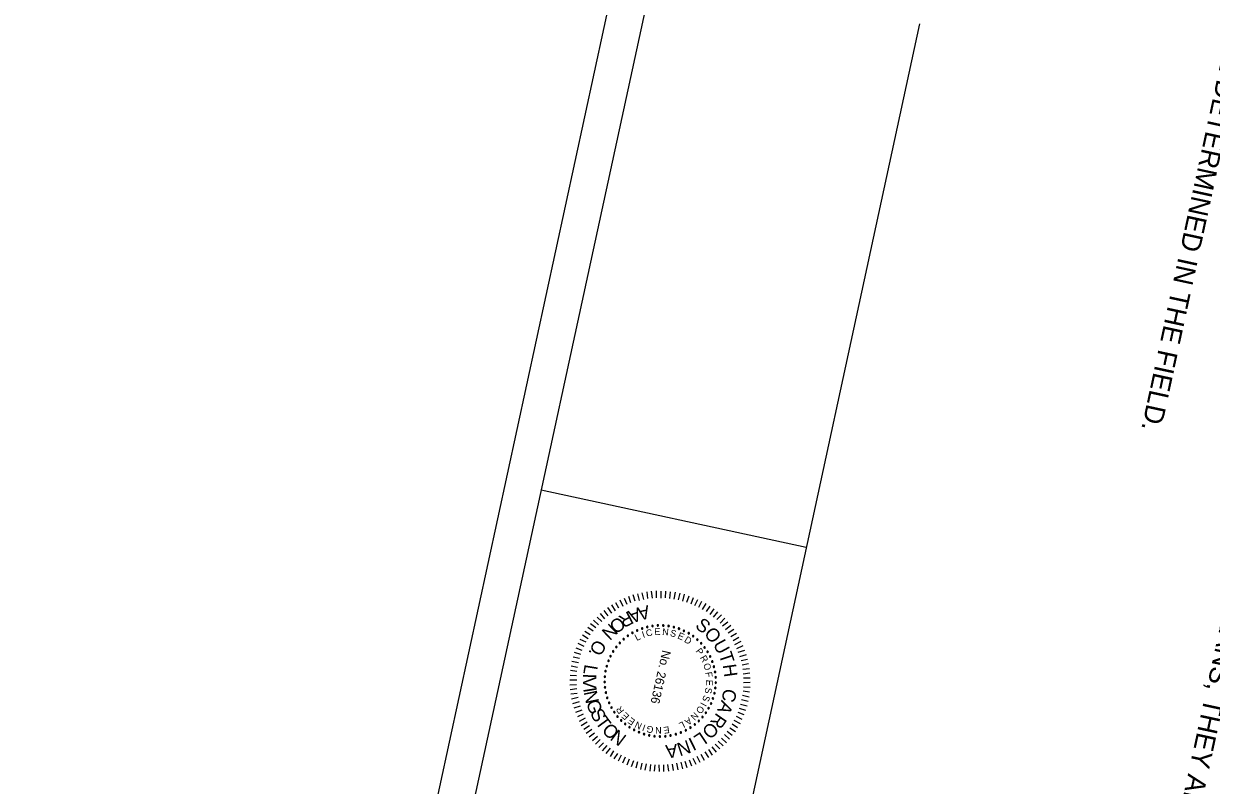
# Model space of a CAD drawing. Extents: x 1897817 to 2050613, y 442539 to 798440.
# Drawn here: x 1976813 to 1977576, y 783723 to 784212 of the extents above; entities that cross this region are included whole.
import ezdxf

# ---------------------------------------------------------------- set-up
doc = ezdxf.new("R2010")
doc.units = 0
for name, color, linetype in [('Default', 7, 'Continuous'), ('RD_SHT_Bndy', 7, 'Continuous'), ('RD_SHT_IplotShp', 7, 'Continuous')]:
    doc.layers.add(name, color=color, linetype=linetype)

msp = doc.modelspace()

# ---------------------------------------------------------------- linework, layer by layer
at = {"layer": 'Default'}
for p, q in [((1977203.28, 783839.73), (1977201.96, 783843.86)), ((1977206.14, 783840.79), (1977204.81, 783844.92)), ((1977208.89, 783841.39), (1977207.72, 783845.67)), ((1977211.58, 783842), (1977210.6, 783846.3)), ((1977214.33, 783842.6), (1977213.77, 783846.86)), ((1977217.12, 783842.82), (1977216.61, 783847.32)), ((1977219.79, 783843.07), (1977219.74, 783847.41)), ((1977222.74, 783842.9), (1977222.76, 783847.33)), ((1977225.56, 783842.99), (1977225.85, 783847.25)), ((1977228.4, 783842.66), (1977228.82, 783846.94)), ((1977231.05, 783842.24), (1977231.91, 783846.61)), ((1977233.97, 783841.71), (1977234.93, 783845.93)), ((1977236.73, 783840.96), (1977237.7, 783845.31)), ((1977239.35, 783840.19), (1977240.75, 783844.26)), ((1977242.07, 783839.27), (1977243.51, 783843.27)), ((1977191.04, 783833.23), (1977188.56, 783836.78)), ((1977193.51, 783834.75), (1977191.12, 783838.45)), ((1977195.7, 783836.32), (1977193.58, 783839.91)), ((1977198.33, 783837.5), (1977196.43, 783841.46)), ((1977200.98, 783838.72), (1977199.25, 783842.64)), ((1977244.34, 783838.03), (1977246.34, 783842.03)), ((1977247.08, 783836.93), (1977248.99, 783840.82)), ((1977249.33, 783835.57), (1977251.77, 783839.4)), ((1977251.87, 783834.15), (1977254.2, 783837.76)), ((1977254.21, 783832.4), (1977256.77, 783835.9)), ((1977182.61, 783825.76), (1977179.43, 783828.67)), ((1977184.65, 783827.8), (1977181.59, 783830.68)), ((1977186.56, 783829.55), (1977183.92, 783832.95)), ((1977188.81, 783831.42), (1977186.24, 783834.86)), ((1977256.44, 783830.68), (1977259.16, 783834.09)), ((1977258.5, 783829), (1977261.46, 783832.17)), ((1977260.63, 783826.82), (1977263.65, 783829.97)), ((1977177.29, 783819.17), (1977173.79, 783821.48)), ((1977179.03, 783821.51), (1977175.63, 783823.98)), ((1977180.75, 783823.74), (1977177.39, 783826.39)), ((1977262.27, 783824.93), (1977265.69, 783827.69)), ((1977264.14, 783822.68), (1977267.5, 783825.46)), ((1977265.9, 783820.52), (1977269.41, 783822.84)), ((1977267.54, 783818.08), (1977271.18, 783820.43)), ((1977173.43, 783811.76), (1977169.48, 783813.68)), ((1977174.52, 783814.44), (1977170.73, 783816.26)), ((1977175.88, 783816.69), (1977172.28, 783819.08)), ((1977268.95, 783815.7), (1977272.6, 783817.85)), ((1977270.14, 783813.11), (1977274.11, 783815.08)), ((1977170.41, 783804.04), (1977166.24, 783804.98)), ((1977171.19, 783806.66), (1977167.08, 783807.89)), ((1977172.08, 783809.26), (1977168.28, 783810.79)), ((1977271.37, 783810.46), (1977275.38, 783812.36)), ((1977272.35, 783808.05), (1977276.47, 783809.32)), ((1977273.43, 783805.31), (1977277.55, 783806.58)), ((1977169.14, 783798.36), (1977164.94, 783799.18)), ((1977169.6, 783801.24), (1977165.49, 783802.17)), ((1977274.13, 783802.72), (1977278.3, 783803.67)), ((1977274.72, 783799.97), (1977278.86, 783800.75)), ((1977275.3, 783797.1), (1977279.56, 783797.66)), ((1977168.54, 783790.04), (1977164.16, 783790.05)), ((1977168.4, 783792.93), (1977164.31, 783793.12)), ((1977168.7, 783795.6), (1977164.46, 783796.25)), ((1977275.57, 783794.24), (1977279.79, 783794.88)), ((1977275.71, 783791.65), (1977280.03, 783791.65)), ((1977168.38, 783787.15), (1977164.15, 783787.01)), ((1977168.63, 783784.48), (1977164.36, 783783.92)), ((1977275.4, 783783.21), (1977279.57, 783782.57)), ((1977275.7, 783785.94), (1977279.96, 783785.65)), ((1977275.78, 783788.72), (1977280, 783788.8)), ((1977168.84, 783781.63), (1977164.69, 783781.04)), ((1977169.45, 783778.94), (1977165.27, 783777.93)), ((1977170.06, 783776.24), (1977165.83, 783775.01)), ((1977273.69, 783774.82), (1977278.01, 783773.73)), ((1977274.5, 783777.63), (1977278.67, 783776.69)), ((1977274.97, 783780.5), (1977279.31, 783779.52)), ((1977170.82, 783773.39), (1977166.69, 783772.07)), ((1977171.81, 783770.8), (1977167.78, 783769.33)), ((1977172.76, 783768.21), (1977168.96, 783766.51)), ((1977270.89, 783766.99), (1977274.68, 783765.17)), ((1977272.03, 783769.6), (1977275.98, 783767.98)), ((1977272.9, 783772.14), (1977276.95, 783770.93)), ((1977174, 783765.62), (1977170.2, 783763.62)), ((1977175.25, 783763.09), (1977171.47, 783760.9)), ((1977176.85, 783760.72), (1977173.13, 783758.51)), ((1977266.85, 783759.57), (1977270.46, 783757.23)), ((1977268.32, 783762.04), (1977271.87, 783759.72)), ((1977269.57, 783764.37), (1977273.45, 783762.4)), ((1977178.16, 783758.41), (1977174.66, 783755.86)), ((1977180, 783756.05), (1977176.63, 783753.53)), ((1977181.89, 783753.92), (1977178.66, 783751.18)), ((1977183.52, 783751.97), (1977180.58, 783748.92)), ((1977261.64, 783752.95), (1977264.81, 783749.98)), ((1977263.43, 783755.22), (1977266.73, 783752.29)), ((1977265.14, 783757.4), (1977268.49, 783754.7)), ((1977185.68, 783749.91), (1977182.72, 783746.8)), ((1977187.89, 783748.13), (1977184.99, 783744.7)), ((1977190.05, 783746.37), (1977187.34, 783742.96)), ((1977192.28, 783744.65), (1977189.97, 783741.15)), ((1977250.88, 783744.05), (1977253.18, 783740.49)), ((1977253.16, 783745.55), (1977255.52, 783741.97)), ((1977255.33, 783747.31), (1977258.07, 783743.83)), ((1977257.56, 783749.12), (1977260.43, 783745.92)), ((1977259.51, 783751.05), (1977262.66, 783747.97)), ((1977194.68, 783743.13), (1977192.36, 783739.58)), ((1977197.01, 783741.88), (1977195.12, 783738.04)), ((1977199.72, 783740.66), (1977197.88, 783736.81)), ((1977202.26, 783739.48), (1977200.72, 783735.63)), ((1977204.93, 783738.39), (1977203.49, 783734.39)), ((1977207.51, 783737.69), (1977206.48, 783733.66)), ((1977210.37, 783736.86), (1977209.45, 783732.75)), ((1977213.19, 783736.41), (1977212.28, 783732.35)), ((1977232.68, 783736.77), (1977233.5, 783732.57)), ((1977235.45, 783737.42), (1977236.43, 783733.12)), ((1977238.04, 783738.12), (1977239.37, 783734.04)), ((1977240.87, 783739.06), (1977242.28, 783735.04)), ((1977243.18, 783740.13), (1977245.1, 783736.22)), ((1977245.8, 783741.24), (1977247.7, 783737.53)), ((1977248.36, 783742.61), (1977250.48, 783738.79)), ((1977215.88, 783735.93), (1977215.42, 783731.71)), ((1977218.76, 783735.76), (1977218.39, 783731.65)), ((1977221.33, 783735.8), (1977221.46, 783731.5)), ((1977224.3, 783735.73), (1977224.37, 783731.46)), ((1977226.89, 783735.88), (1977227.52, 783731.66)), ((1977229.82, 783736.2), (1977230.4, 783732.05))]:
    msp.add_line(p, q, dxfattribs=at)
for centre, start, end in [((1977204.29, 783820.49), 30.23602, 210.23602), ((1977204.29, 783820.49), 210.23602, 30.23602), ((1977207.35, 783822.07), 24.69756, 204.69756), ((1977207.35, 783822.07), 204.69756, 24.69756), ((1977210.55, 783823.35), 19.15909, 199.15909), ((1977210.55, 783823.35), 199.15909, 19.15909), ((1977213.86, 783824.32), 13.62063, 193.62063), ((1977213.86, 783824.32), 193.62063, 13.62063), ((1977217.25, 783824.96), 8.08217, 188.08217), ((1977217.25, 783824.96), 188.08217, 8.08217), ((1977220.68, 783825.27), 2.54371, 182.54371), ((1977220.68, 783825.27), 182.54371, 2.54371), ((1977224.13, 783825.25), 177.00525, 357.00525), ((1977224.13, 783825.25), 357.00525, 177.00525), ((1977227.56, 783824.9), 171.46679, 351.46679), ((1977227.56, 783824.9), 351.46679, 171.46679), ((1977230.94, 783824.22), 165.92833, 345.92833), ((1977230.94, 783824.22), 345.92833, 165.92833), ((1977234.24, 783823.21), 160.38986, 340.38986), ((1977234.24, 783823.21), 340.38986, 160.38986), ((1977237.42, 783821.89), 154.8514, 334.8514), ((1977237.42, 783821.89), 334.8514, 154.8514), ((1977240.47, 783820.27), 149.31294, 329.31294), ((1977240.47, 783820.27), 329.31294, 149.31294), ((1977196.21, 783814.08), 46.8514, 226.8514), ((1977196.21, 783814.08), 226.8514, 46.8514), ((1977198.69, 783816.47), 41.31294, 221.31294), ((1977198.69, 783816.47), 221.31294, 41.31294), ((1977201.39, 783818.61), 35.77448, 215.77448), ((1977201.39, 783818.61), 215.77448, 35.77448), ((1977243.34, 783818.37), 143.77448, 323.77448), ((1977243.34, 783818.37), 323.77448, 143.77448), ((1977246.01, 783816.19), 138.23602, 318.23602), ((1977246.01, 783816.19), 318.23602, 138.23602), ((1977248.47, 783813.77), 132.69756, 312.69756), ((1977248.47, 783813.77), 312.69756, 132.69756), ((1977190.3, 783805.63), 63.46679, 243.46679), ((1977190.3, 783805.63), 243.46679, 63.46679), ((1977192, 783808.63), 57.92833, 237.92833), ((1977192, 783808.63), 237.92833, 57.92833), ((1977193.97, 783811.46), 52.38986, 232.38986), ((1977193.97, 783811.46), 232.38986, 52.38986), ((1977250.67, 783811.12), 127.15909, 307.15909), ((1977250.67, 783811.12), 307.15909, 127.15909), ((1977252.62, 783808.27), 121.62063, 301.62063), ((1977252.62, 783808.27), 301.62063, 121.62063), ((1977254.27, 783805.25), 116.08217, 296.08217), ((1977254.27, 783805.25), 296.08217, 116.08217), ((1977187.82, 783799.2), 74.54371, 254.54371), ((1977187.82, 783799.2), 254.54371, 74.54371), ((1977188.91, 783802.47), 69.00525, 249.00525), ((1977188.91, 783802.47), 249.00525, 69.00525), ((1977255.63, 783802.08), 110.54371, 290.54371), ((1977255.63, 783802.08), 290.54371, 110.54371), ((1977256.68, 783798.79), 105.00525, 285.00525), ((1977256.68, 783798.79), 285.00525, 105.00525), ((1977186.62, 783792.42), 85.62063, 265.62063), ((1977187.06, 783795.84), 80.08217, 260.08217), ((1977186.62, 783792.42), 265.62063, 85.62063), ((1977187.06, 783795.84), 260.08217, 80.08217), ((1977257.4, 783795.42), 99.46679, 279.46679), ((1977257.8, 783792), 93.92833, 273.92833), ((1977257.4, 783795.42), 279.46679, 99.46679), ((1977257.8, 783792), 273.92833, 93.92833), ((1977186.52, 783788.97), 91.15909, 271.15909), ((1977186.75, 783785.53), 96.69756, 276.69756), ((1977186.52, 783788.97), 271.15909, 91.15909), ((1977186.75, 783785.53), 276.69756, 96.69756), ((1977187.31, 783782.13), 102.23602, 282.23602), ((1977187.31, 783782.13), 282.23602, 102.23602), ((1977256.99, 783781.72), 77.31294, 257.31294), ((1977256.99, 783781.72), 257.31294, 77.31294), ((1977257.59, 783785.11), 82.8514, 262.8514), ((1977257.86, 783788.55), 88.38986, 268.38986), ((1977257.59, 783785.11), 262.8514, 82.8514), ((1977257.86, 783788.55), 268.38986, 88.38986), ((1977188.2, 783778.8), 107.77448, 287.77448), ((1977188.2, 783778.8), 287.77448, 107.77448), ((1977189.4, 783775.57), 113.31294, 293.31294), ((1977189.4, 783775.57), 293.31294, 113.31294), ((1977254.82, 783775.18), 66.23602, 246.23602), ((1977254.82, 783775.18), 246.23602, 66.23602), ((1977256.06, 783778.4), 71.77448, 251.77448), ((1977256.06, 783778.4), 251.77448, 71.77448), ((1977190.91, 783772.47), 118.8514, 298.8514), ((1977190.91, 783772.47), 298.8514, 118.8514), ((1977192.71, 783769.53), 124.38986, 304.38986), ((1977192.71, 783769.53), 304.38986, 124.38986), ((1977194.79, 783766.78), 129.92833, 309.92833), ((1977194.79, 783766.78), 309.92833, 129.92833), ((1977249.33, 783766.46), 49.62063, 229.62063), ((1977249.33, 783766.46), 229.62063, 49.62063), ((1977251.44, 783769.18), 55.15909, 235.15909), ((1977251.44, 783769.18), 235.15909, 55.15909), ((1977253.28, 783772.1), 60.69756, 240.69756), ((1977253.28, 783772.1), 240.69756, 60.69756), ((1977197.12, 783764.24), 135.46679, 315.46679), ((1977197.12, 783764.24), 315.46679, 135.46679), ((1977199.69, 783761.94), 141.00525, 321.00525), ((1977199.69, 783761.94), 321.00525, 141.00525), ((1977202.46, 783759.9), 146.54371, 326.54371), ((1977202.46, 783759.9), 326.54371, 146.54371), ((1977241.57, 783759.66), 33.00525, 213.00525), ((1977241.57, 783759.66), 213.00525, 33.00525), ((1977244.37, 783761.67), 38.54371, 218.54371), ((1977244.37, 783761.67), 218.54371, 38.54371), ((1977246.97, 783763.94), 44.08217, 224.08217), ((1977246.97, 783763.94), 224.08217, 44.08217), ((1977205.43, 783758.13), 152.08217, 332.08217), ((1977205.43, 783758.13), 332.08217, 152.08217), ((1977208.54, 783756.66), 157.62063, 337.62063), ((1977208.54, 783756.66), 337.62063, 157.62063), ((1977211.79, 783755.5), 163.15909, 343.15909), ((1977211.79, 783755.5), 343.15909, 163.15909), ((1977215.13, 783754.65), 168.69756, 348.69756), ((1977215.13, 783754.65), 348.69756, 168.69756), ((1977218.54, 783754.13), 354.23602, 174.23602), ((1977218.54, 783754.13), 174.23602, 354.23602), ((1977221.98, 783753.94), 359.77448, 179.77448), ((1977221.98, 783753.94), 179.77448, 359.77448), ((1977225.43, 783754.09), 5.31294, 185.31294), ((1977225.43, 783754.09), 185.31294, 5.31294), ((1977228.84, 783754.57), 10.8514, 190.8514), ((1977228.84, 783754.57), 190.8514, 10.8514), ((1977232.19, 783755.37), 16.38986, 196.38986), ((1977232.19, 783755.37), 196.38986, 16.38986), ((1977235.45, 783756.5), 21.92833, 201.92833), ((1977235.45, 783756.5), 201.92833, 21.92833), ((1977238.59, 783757.93), 27.46679, 207.46679), ((1977238.59, 783757.93), 207.46679, 27.46679)]:
    msp.add_arc(centre, 0.485, start, end, dxfattribs=at)
at = {"layer": 'RD_SHT_Bndy'}
for p, q in [((1977385.46, 785019.62), (1976842.49, 782511.26)), ((1977388.81, 784211.78), (1977012.76, 782474.48)), ((1977316, 783875.38), (1977145.75, 783912.23))]:
    msp.add_line(p, q, dxfattribs=at)
at = {"layer": 'RD_SHT_IplotShp'}
msp.add_lwpolyline([(1977366.14, 785041.72), (1976813.35, 782487.96), (1978459.81, 782131.57), (1979012.6, 784685.33)], close=True, dxfattribs=at)

# ---------------------------------------------------------------- texts
at = {"layer": 'Default'}
for s, height, rotation, p in [('ALL PLANS ARE SCHEMATIC IN NATURE. EXACT LOCATIONS SHALL BE DETERMINED IN THE FIELD.', 12.7057, 257.78611, (1977704.91, 784754.25)), ('ITS DEVICES/SYMBOLOGY (CAMERA, SERVICE BOX, DMS, CABINET, ETC.) ARE SCALED UP FOR VISIBILITY ON PLANS, THEY ARE', 12.70566, 257.78611, (1977779.42, 784738.12)), ('A', 8.55, 200.07535, (1977208.05, 783836.96)), ('A', 8.55, 192.51585, (1977214.41, 783838.37)), ('O', 8.55, 215.57222, (1977195.87, 783831.52)), ('R', 8.55, 207.63485, (1977201.92, 783834.72)), ('S', 8.57, 321.03725, (1977244.08, 783824.29)), ('N', 8.55, 224.25857, (1977189.81, 783827.1)), ('I', 4.31, 18.88718, (1977211.29, 783817.19)), ('C', 4.31, 14.21273, (1977213.57, 783817.98)), ('E', 4.31, 4.32163, (1977218.58, 783819.01)), ('N', 4.31, 355.11927, (1977223.33, 783819.18)), ('S', 4.31, 345.57209, (1977228.22, 783818.56)), ('E', 4.31, 336.02491, (1977232.94, 783817.14)), ('O', 8.58, 309.8128, (1977249.88, 783819.82)), ('O', 8.55, 240.13332, (1977180.75, 783816.88)), ('L', 4.31, 27.74562, (1977207.17, 783815.21)), ('D', 4.31, 326.82255, (1977237.2, 783815.04)), ('U', 8.58, 298.58836, (1977255.82, 783813.26)), ('.', 8.55, 248.81967, (1977177.08, 783810.35)), ('No. 26136', 5.656, 257.31294, (1977223.6, 783809.73)), ('P', 4.31, 307.7282, (1977244.69, 783808.68)), ('R', 4.31, 298.18102, (1977247.55, 783804.66)), ('T', 8.58, 288.28532, (1977259.68, 783806.68)), ('L', 8.55, 260.75383, (1977173.74, 783800.62)), ('O', 4.31, 288.63384, (1977249.69, 783800.22)), ('H', 8.58, 278.14982, (1977262.29, 783799.89)), ('V', 8.55, 270.56025, (1977172.54, 783792.25)), ('I', 8.55, 267.93836, (1977172.72, 783794.51)), ('F', 4.31, 278.39882, (1977251.14, 783795.14)), ('E', 4.31, 269.19645, (1977251.65, 783790.41)), ('I', 8.55, 279.2466, (1977172.69, 783784.76)), ('N', 8.55, 281.86849, (1977172.96, 783782.51)), ('S', 4.31, 259.99409, (1977251.4, 783785.66)), ('C', 8.58, 257.33433, (1977263.24, 783785.21)), ('G', 8.55, 289.80587, (1977174.39, 783775.82)), ('I', 4.31, 240.89974, (1977248.51, 783776.27)), ('S', 4.31, 250.44691, (1977250.35, 783780.85)), ('A', 8.58, 245.98424, (1977261.66, 783777.67)), ('S', 8.55, 298.11724, (1977176.86, 783769.09)), ('T', 8.55, 306.05462, (1977180.11, 783763.06)), ('R', 4.31, 127.56812, (1977199.33, 783770.56)), ('E', 4.31, 136.77048, (1977202.67, 783767.17)), ('N', 4.31, 225.99026, (1977244.19, 783769.91)), ('O', 4.31, 236.22529, (1977247.33, 783774.16)), ('R', 8.58, 235.2205, (1977258.51, 783769.63)), ('O', 8.55, 313.99199, (1977184.16, 783757.54)), ('E', 4.31, 145.97284, (1977206.5, 783764.36)), ('N', 4.31, 155.52002, (1977210.9, 783762.14)), ('I', 4.31, 160.19447, (1977213.18, 783761.32)), ('G', 4.31, 170.08557, (1977218.16, 783760.22)), ('N', 4.31, 179.63275, (1977223.09, 783759.98)), ('E', 4.31, 188.83511, (1977227.81, 783760.53)), ('L', 4.31, 207.24072, (1977236.69, 783763.84)), ('A', 4.31, 216.44308, (1977240.62, 783766.51)), ('O', 8.57, 224.373, (1977254.68, 783763.92)), ('N', 8.55, 322.67834, (1977189.41, 783752.2)), ('N', 8.58, 198.48976, (1977239.94, 783751.93)), ('I', 8.58, 206.44739, (1977242.38, 783753.57)), ('L', 8.58, 213.7349, (1977248.45, 783757.31)), ('A', 8.58, 187.26532, (1977232.78, 783749.28))]:
    msp.add_text(s, height=height, rotation=rotation, dxfattribs=at).set_placement(p)

doc.saveas('drawing.dxf')
